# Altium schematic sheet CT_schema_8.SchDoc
size 274 x 160 mm
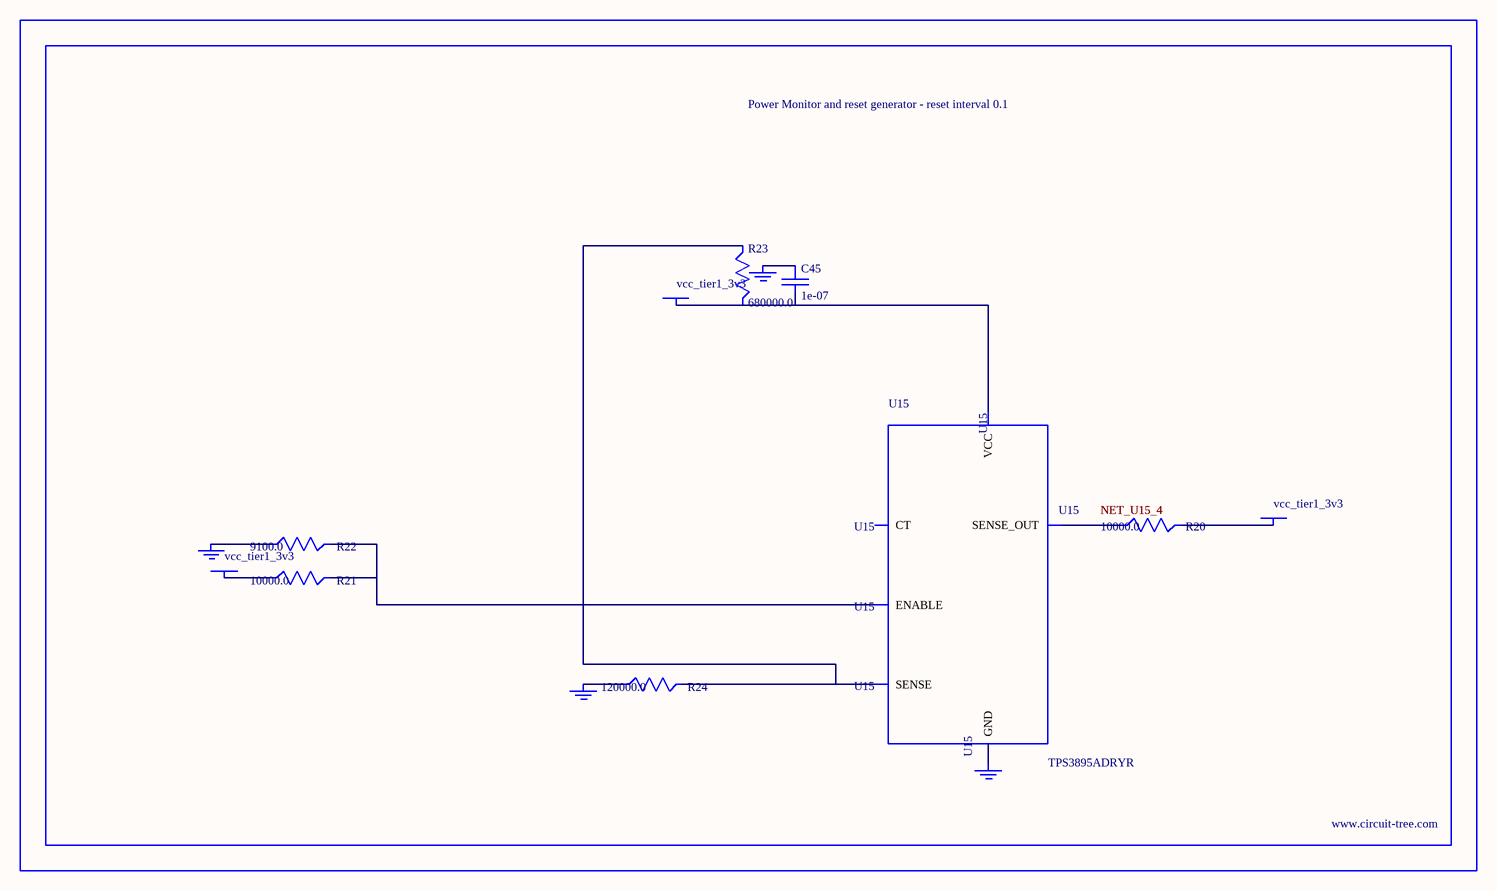
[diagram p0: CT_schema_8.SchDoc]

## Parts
BORDER7  (no value)
C45  1e-07  [C0402]
GND_INSTANCE_7_0  (no value)
GND_INSTANCE_7_1  (no value)
GND_INSTANCE_7_2  (no value)
GND_INSTANCE_7_3  (no value)
POWER_INSTANCE_7_0  vcc_tier1_3v3
POWER_INSTANCE_7_1  vcc_tier1_3v3
POWER_INSTANCE_7_2  vcc_tier1_3v3
R20  10000.0  [R0603]
R21  10000.0  [R0603]
R22  9100.0  [R0603]
R23  680000.0  [R0603]
R24  120000.0  [R0603]
U15  TPS3895ADRYR  [SON-6]

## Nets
NetC45_1: C45.1 GND_INSTANCE_7_2.0(GND)
NetC45_2: C45.2 POWER_INSTANCE_7_2.0(PWR) R23.2 U15.6(VCC)
NetGND_INSTANCE_7_0_0: GND_INSTANCE_7_0.0(GND) R22.1
NetGND_INSTANCE_7_1_0: GND_INSTANCE_7_1.0(GND) R24.1
NetGND_INSTANCE_7_3_0: GND_INSTANCE_7_3.0(GND) U15.2(GND)
NetPOWER_INSTANCE_7_0_0: POWER_INSTANCE_7_0.0(PWR) R21.1
NetPOWER_INSTANCE_7_1_0: POWER_INSTANCE_7_1.0(PWR) R20.2
NetR20_1: R20.1 U15.4(SENSE_OUT)
NetR21_2: R21.2 R22.2 U15.1(ENABLE)
NetR23_1: R23.1 R24.2 U15.3(SENSE)

Not connected (* = marked no-connect by the designer): U15 5(CT)

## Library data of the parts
BORDER7 = BORDER_PAGE7
C45 = C0402C104K3RACTU
GND_INSTANCE_7_0-GND_INSTANCE_7_3 = GND
POWER_INSTANCE_7_0-POWER_INSTANCE_7_2 = PWR
R20 R21 = RC0603JR-0710KL
R22 = RC0603JR-079K1L
R23 = RC0603JR-07680KL
R24 = RC0603JR-07120KL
